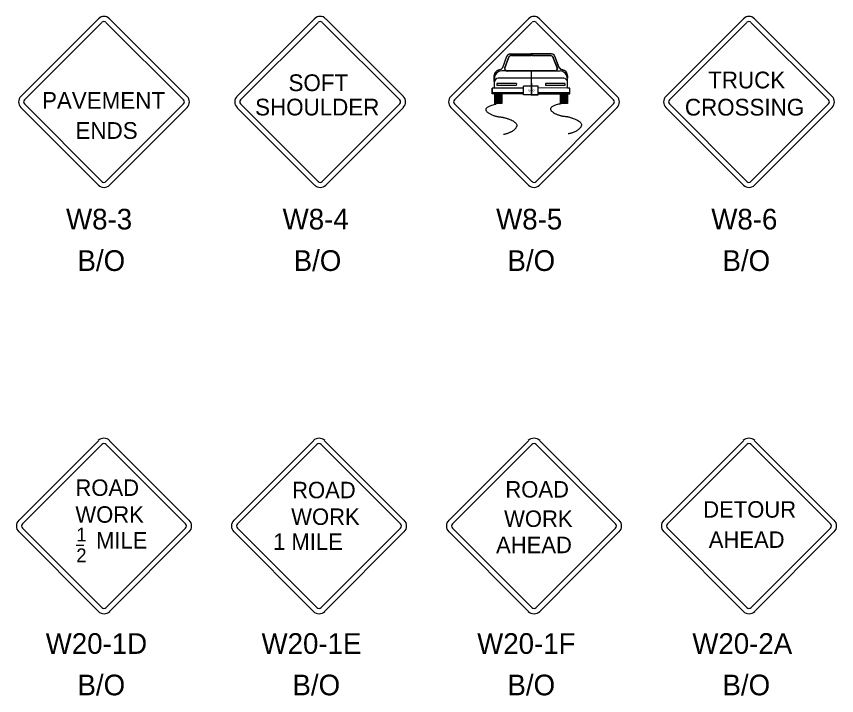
# Model space of a CAD drawing. Extents: x 10034 to 10794, y 10044 to 10499.
# Drawn here: x 10507.5 to 10646.3, y 10279.5 to 10394.4 of the extents above; entities that cross this region are included whole.
import ezdxf

# ---------------------------------------------------------------- set-up
doc = ezdxf.new("R2010")
doc.units = 0
for name, color, linetype in [('DSIndex', 7, 'Continuous'), ('DSText', 7, 'Continuous'), ('DSTitle', 7, 'Continuous'), ('PlotBorder_dp', 7, 'Continuous')]:
    doc.layers.add(name, color=color, linetype=linetype)

msp = doc.modelspace()

# ---------------------------------------------------------------- linework, layer by layer
at = {"layer": 'DSIndex'}
for p, q in [((10508.21, 10380.84), (10521.36, 10393.99)), ((10508.82, 10380.24), (10521.95, 10393.37)), ((10522.63, 10393.37), (10535.76, 10380.24)), ((10523.23, 10393.99), (10536.37, 10380.84)), ((10581, 10380.84), (10594.15, 10393.99)), ((10581.61, 10380.25), (10594.74, 10393.37)), ((10595.42, 10393.37), (10608.55, 10380.25)), ((10596.02, 10393.99), (10609.16, 10380.84)), ((10589.8, 10385.74), (10590.5, 10387.62)), ((10591.08, 10388.02), (10594.55, 10388.02)), ((10591.33, 10387.78), (10594.55, 10387.78)), ((10598.04, 10388.02), (10594.55, 10388.02)), ((10597.77, 10387.78), (10594.55, 10387.78)), ((10599.32, 10385.74), (10598.61, 10387.62)), ((10590.13, 10385.7), (10590.76, 10387.38)), ((10598.98, 10385.7), (10598.35, 10387.38)), ((10598.59, 10385.14), (10589.62, 10385.14)), ((10598.59, 10385.14), (10599.49, 10385.14)), ((10588.36, 10384.36), (10588.39, 10383.91)), ((10588.38, 10383.3), (10588.39, 10383.91)), ((10600.11, 10383.91), (10589, 10383.91)), ((10600.75, 10384.31), (10600.73, 10383.91)), ((10600.73, 10383.29), (10600.73, 10383.91)), ((10587.97, 10382.26), (10587.97, 10381.28)), ((10593.32, 10382.26), (10587.97, 10382.26)), ((10588.38, 10382.27), (10588.38, 10383.3)), ((10592.09, 10383), (10588.79, 10383)), ((10588.79, 10383), (10588.8, 10382.67)), ((10592.08, 10382.67), (10588.8, 10382.67)), ((10592.09, 10383), (10592.08, 10382.67)), ((10593.32, 10381.11), (10593.32, 10382.6)), ((10595.79, 10382.6), (10593.32, 10382.6)), ((10595.79, 10381.11), (10595.79, 10382.6)), ((10601.14, 10382.26), (10595.79, 10382.27)), ((10600.32, 10383), (10597.02, 10383)), ((10597.02, 10383), (10597.02, 10382.67)), ((10600.31, 10382.67), (10597.02, 10382.67)), ((10600.32, 10383), (10600.31, 10382.67)), ((10600.73, 10382.26), (10600.73, 10383.29)), ((10601.14, 10381.28), (10601.14, 10382.26)), ((10593.32, 10381.44), (10587.97, 10381.44)), ((10593.32, 10381.28), (10587.97, 10381.28)), ((10588.38, 10381.28), (10588.39, 10379.63)), ((10588.59, 10381.28), (10588.59, 10379.63)), ((10588.8, 10381.28), (10588.79, 10379.63)), ((10589, 10381.28), (10589, 10379.63)), ((10589.21, 10381.28), (10589.21, 10379.63)), ((10589.41, 10381.27), (10589.41, 10379.63)), ((10589.62, 10381.28), (10589.62, 10379.63)), ((10595.79, 10381.11), (10593.32, 10381.11)), ((10601.14, 10381.44), (10595.79, 10381.44)), ((10601.14, 10381.28), (10595.79, 10381.28)), ((10599.49, 10381.28), (10599.49, 10379.63)), ((10599.7, 10381.28), (10599.7, 10379.63)), ((10599.9, 10381.28), (10599.9, 10379.63)), ((10600.11, 10381.28), (10600.11, 10379.63)), ((10600.31, 10381.28), (10600.31, 10379.63)), ((10600.52, 10381.28), (10600.52, 10379.63)), ((10600.73, 10381.28), (10600.73, 10379.63)), ((10521.95, 10366.44), (10508.82, 10379.57)), ((10535.76, 10379.57), (10522.63, 10366.44)), ((10594.74, 10366.44), (10581.61, 10379.57)), ((10589.62, 10379.63), (10588.39, 10379.63)), ((10608.55, 10379.57), (10595.42, 10366.44)), ((10600.73, 10379.63), (10599.49, 10379.63)), ((10521.36, 10365.82), (10508.21, 10378.97)), ((10536.37, 10378.97), (10523.23, 10365.82)), ((10594.15, 10365.83), (10581, 10378.97)), ((10609.16, 10378.97), (10596.02, 10365.83)), ((10507.86, 10309.13), (10521.34, 10322.61)), ((10523.25, 10322.61), (10536.73, 10309.13)), ((10508.49, 10308.52), (10521.94, 10321.98)), ((10522.64, 10321.98), (10536.1, 10308.52)), ((10521.34, 10293.74), (10507.86, 10307.22)), ((10521.94, 10294.37), (10508.49, 10307.83)), ((10536.1, 10307.83), (10522.64, 10294.37)), ((10536.73, 10307.22), (10523.25, 10293.74)), ((10517.56, 10304.94), (10518.87, 10304.94))]:
    msp.add_line(p, q, dxfattribs=at)
for points in [[(10594.63, 10381.09), (10593.32, 10381.11), (10593.32, 10381.28), (10587.97, 10381.28), (10587.97, 10382.26), (10588.38, 10382.27), (10588.36, 10384.36), (10588.39, 10384.5), (10588.4, 10384.61), (10588.45, 10384.73), (10588.53, 10384.88), (10588.6, 10385), (10588.68, 10385.07), (10588.8, 10385.17), (10588.91, 10385.24), (10588.99, 10385.27), (10589.07, 10385.3), (10589.24, 10385.34), (10589.37, 10385.39), (10589.47, 10385.44), (10589.55, 10385.51), (10589.63, 10385.56), (10589.71, 10385.64), (10589.75, 10385.68), (10589.8, 10385.74), (10590.5, 10387.62), (10590.55, 10387.72), (10590.6, 10387.81), (10590.67, 10387.86), (10590.75, 10387.91), (10590.81, 10387.96), (10590.89, 10387.99), (10591.02, 10388.02), (10591.08, 10388.02), (10594.7, 10388.02), (10594.69, 10387.78), (10591.33, 10387.78), (10591.22, 10387.76), (10591.13, 10387.73), (10591.05, 10387.7), (10590.99, 10387.65), (10590.92, 10387.62), (10590.86, 10387.58), (10590.81, 10387.51), (10590.76, 10387.38), (10590.13, 10385.7), (10590.11, 10385.59), (10590.12, 10385.48), (10590.17, 10385.37), (10590.22, 10385.25), (10590.32, 10385.19), (10590.41, 10385.14), (10590.6, 10385.13), (10594.6, 10385.14)], [(10594.62, 10381.11), (10595.79, 10381.11), (10595.79, 10381.28), (10601.14, 10381.28), (10601.14, 10382.26), (10600.73, 10382.26), (10600.73, 10383.91), (10600.72, 10384.04), (10600.73, 10384.15), (10600.74, 10384.33), (10600.73, 10384.48), (10600.71, 10384.63), (10600.66, 10384.73), (10600.61, 10384.85), (10600.51, 10384.98), (10600.41, 10385.1), (10600.32, 10385.18), (10600.19, 10385.23), (10600.03, 10385.3), (10599.92, 10385.33), (10599.74, 10385.38), (10599.63, 10385.44), (10599.53, 10385.52), (10599.44, 10385.64), (10599.34, 10385.71), (10599.31, 10385.74), (10598.61, 10387.62), (10598.56, 10387.7), (10598.51, 10387.78), (10598.48, 10387.85), (10598.42, 10387.91), (10598.33, 10387.94), (10598.24, 10387.98), (10598.04, 10388.02), (10594.69, 10388.01), (10594.71, 10387.78), (10597.77, 10387.78), (10597.89, 10387.77), (10597.98, 10387.74), (10598.07, 10387.68), (10598.18, 10387.63), (10598.27, 10387.55), (10598.32, 10387.47), (10598.35, 10387.38), (10598.98, 10385.7), (10598.98, 10385.62), (10599.01, 10385.54), (10599, 10385.47), (10598.98, 10385.4), (10598.94, 10385.34), (10598.9, 10385.29), (10598.87, 10385.22), (10598.76, 10385.17), (10598.73, 10385.17), (10598.64, 10385.13), (10594.59, 10385.13)]]:
    msp.add_lwpolyline(points, close=True, dxfattribs=at)
for centre, radius, start, end in [((10522.29, 10393.05), 1.32, 45, 135), ((10522.29, 10393.04), 0.478, 45, 135), ((10595.08, 10393.05), 1.32, 45, 135), ((10595.08, 10393.04), 0.478, 45, 135), ((10591.07, 10387.41), 0.617, 89.9999, 159.5728), ((10591.33, 10387.16), 0.617, 89.9999, 159.5806), ((10597.77, 10387.16), 0.617, 20.4192, 89.9999), ((10589.39, 10384.33), 1.03, 102.0025, 178.0644), ((10589.62, 10383.91), 1.23, 89.9999, 179.9999), ((10588.96, 10386.34), 1.03, 281.9867, 324.0057), ((10590.52, 10385.55), 0.411, 159.5922, 269.9999), ((10598.59, 10385.55), 0.411, 269.9999, 20.4076), ((10600.14, 10386.34), 1.03, 215.9941, 258.0132), ((10599.49, 10383.91), 1.23, 359.9999, 89.9999), ((10599.72, 10384.33), 1.03, 358.9918, 77.9966), ((10589, 10383.29), 0.617, 89.9999, 179.9999), ((10600.11, 10383.29), 0.617, 359.9999, 89.9999), ((10509.15, 10379.91), 1.32, 135, 225), ((10535.43, 10379.91), 1.32, 315, 45), ((10581.94, 10379.91), 1.32, 135, 225), ((10608.22, 10379.91), 1.32, 315, 45), ((10509.16, 10379.91), 0.478, 135, 225), ((10535.43, 10379.91), 0.478, 315, 45), ((10581.95, 10379.91), 0.478, 135, 225), ((10608.21, 10379.91), 0.478, 315, 45), ((10522.3, 10366.76), 1.32, 225, 315), ((10522.29, 10366.77), 0.478, 225, 315), ((10595.08, 10366.76), 1.32, 225, 315), ((10595.08, 10366.77), 0.478, 225, 315), ((10522.29, 10321.65), 1.36, 45, 135), ((10522.29, 10321.64), 0.49, 45, 135), ((10508.82, 10308.18), 1.36, 135, 225), ((10508.83, 10308.18), 0.49, 135, 225), ((10535.75, 10308.18), 0.49, 315, 45), ((10535.76, 10308.18), 1.36, 315, 45), ((10522.3, 10294.7), 1.36, 225, 315), ((10522.29, 10294.72), 0.49, 225, 315)]:
    msp.add_arc(centre, radius, start, end, dxfattribs=at)
for points in [[(10588.7, 10379.5), (10586.27, 10378.98), (10588.08, 10377.42), (10589.88, 10377.32)], [(10599.64, 10379.6), (10597.22, 10379.08), (10599.02, 10377.52), (10600.83, 10377.42)], [(10589.73, 10377.34), (10592.53, 10376.62), (10591.69, 10374.77), (10589.91, 10374.39)], [(10600.68, 10377.44), (10603.48, 10376.72), (10602.64, 10374.87), (10600.85, 10374.49)]]:
    msp.add_open_spline(points, degree=2, dxfattribs=at)
at = {"layer": 'DSText'}
for p, q in [((10544.8, 10380.84), (10557.95, 10393.99)), ((10559.82, 10393.99), (10572.97, 10380.84)), ((10617.39, 10380.84), (10630.54, 10393.99)), ((10632.41, 10393.99), (10645.55, 10380.84)), ((10557.95, 10365.82), (10544.8, 10378.97)), ((10572.97, 10378.97), (10559.82, 10365.82)), ((10630.54, 10365.82), (10617.39, 10378.97)), ((10645.55, 10378.97), (10632.41, 10365.82)), ((10544.25, 10309.13), (10557.73, 10322.61)), ((10559.64, 10322.61), (10573.12, 10309.13)), ((10580.65, 10309.13), (10594.12, 10322.61)), ((10596.04, 10322.61), (10609.51, 10309.13)), ((10617.04, 10309.13), (10630.52, 10322.61)), ((10632.43, 10322.61), (10645.91, 10309.13)), ((10557.73, 10293.74), (10544.25, 10307.22)), ((10573.12, 10307.22), (10559.64, 10293.74)), ((10594.12, 10293.74), (10580.65, 10307.22)), ((10609.51, 10307.22), (10596.04, 10293.74)), ((10630.52, 10293.74), (10617.04, 10307.22)), ((10645.91, 10307.22), (10632.43, 10293.74))]:
    msp.add_line(p, q, dxfattribs=at)
for centre, radius, start, end in [((10558.88, 10393.05), 1.32, 45, 135), ((10631.47, 10393.05), 1.32, 45, 135), ((10545.74, 10379.91), 1.32, 135, 225), ((10572.02, 10379.91), 1.32, 315, 45), ((10618.33, 10379.91), 1.32, 135, 225), ((10644.61, 10379.91), 1.32, 315, 45), ((10558.89, 10366.76), 1.32, 225, 315), ((10631.48, 10366.76), 1.32, 225, 315), ((10558.69, 10321.65), 1.36, 45, 135), ((10595.08, 10321.65), 1.36, 45, 135), ((10631.47, 10321.65), 1.36, 45, 135), ((10545.22, 10308.18), 1.36, 135, 225), ((10572.16, 10308.18), 1.36, 315, 45), ((10581.61, 10308.18), 1.36, 135, 225), ((10608.55, 10308.18), 1.36, 315, 45), ((10618, 10308.18), 1.36, 135, 225), ((10644.94, 10308.18), 1.36, 315, 45), ((10558.69, 10294.7), 1.36, 225, 315), ((10595.08, 10294.7), 1.36, 225, 315), ((10631.48, 10294.7), 1.36, 225, 315)]:
    msp.add_arc(centre, radius, start, end, dxfattribs=at)
at = {"layer": 'DSTitle'}
for p, q in [((10545.42, 10380.24), (10558.55, 10393.37)), ((10559.23, 10393.37), (10572.35, 10380.24)), ((10618, 10380.24), (10631.13, 10393.37)), ((10631.81, 10393.37), (10644.94, 10380.24)), ((10558.55, 10366.44), (10545.42, 10379.56)), ((10572.35, 10379.56), (10559.23, 10366.44)), ((10631.13, 10366.44), (10618, 10379.57)), ((10644.94, 10379.57), (10631.81, 10366.44)), ((10544.88, 10308.52), (10558.34, 10321.98)), ((10559.03, 10321.98), (10572.49, 10308.52)), ((10581.27, 10308.52), (10594.73, 10321.98)), ((10595.43, 10321.98), (10608.89, 10308.52)), ((10617.67, 10308.52), (10631.12, 10321.98)), ((10631.82, 10321.98), (10645.28, 10308.52)), ((10558.34, 10294.37), (10544.88, 10307.83)), ((10572.49, 10307.83), (10559.03, 10294.37)), ((10594.73, 10294.37), (10581.27, 10307.83)), ((10608.89, 10307.83), (10595.43, 10294.37)), ((10631.12, 10294.37), (10617.67, 10307.83)), ((10645.28, 10307.83), (10631.82, 10294.37))]:
    msp.add_line(p, q, dxfattribs=at)
for centre, radius, start, end in [((10558.88, 10393.04), 0.478, 45, 135), ((10631.47, 10393.04), 0.478, 45, 135), ((10545.75, 10379.91), 0.478, 135, 225), ((10572.02, 10379.91), 0.478, 315, 45), ((10618.34, 10379.91), 0.478, 135, 225), ((10644.6, 10379.91), 0.478, 315, 45), ((10558.88, 10366.77), 0.478, 225, 315), ((10631.47, 10366.77), 0.478, 225, 315), ((10558.69, 10321.64), 0.49, 45, 135), ((10595.08, 10321.64), 0.49, 45, 135), ((10631.47, 10321.64), 0.49, 45, 135), ((10545.23, 10308.18), 0.49, 135, 225), ((10572.15, 10308.18), 0.49, 315, 45), ((10581.62, 10308.18), 0.49, 135, 225), ((10608.54, 10308.18), 0.49, 315, 45), ((10618.01, 10308.18), 0.49, 135, 225), ((10644.93, 10308.18), 0.49, 315, 45), ((10558.69, 10294.72), 0.49, 225, 315), ((10595.08, 10294.72), 0.49, 225, 315), ((10631.47, 10294.72), 0.49, 225, 315)]:
    msp.add_arc(centre, radius, start, end, dxfattribs=at)

# ---------------------------------------------------------------- texts
at = {"layer": 'DSIndex'}
for s, height, p in [('PAVEMENT', 2.831, (10511.8, 10378.75)), ('ENDS', 2.831, (10517.47, 10373.66)), ('W8-3', 3.5, (10515.87, 10358.33)), ('W8-5', 3.5, (10588.67, 10358.33)), ('B/O', 3.5, (10517.81, 10351.32)), ('B/O', 3.5, (10590.59, 10351.32)), ('ROAD', 2.786, (10517.46, 10313.27)), ('WORK', 2.786, (10517.45, 10308.73)), ('1', 2.32, (10517.61, 10305.57)), ('MILE', 2.786, (10520.95, 10304.36)), ('2', 2.32, (10517.61, 10302.06)), ('W20-1D', 3.5, (10512.43, 10286.55)), ('B/O', 3.5, (10517.81, 10279.54))]:
    msp.add_text(s, height=height, dxfattribs=at).set_placement(p)
msp.add_text('GKO', height=0.348, rotation=0.009, dxfattribs=at).set_placement((10594.1, 10381.7))
at = {"layer": 'PlotBorder_dp'}
for s, height, p in [('TRUCK', 2.831, (10624.56, 10382.2)), ('SOFT', 2.831, (10553.52, 10381.74)), ('SHOULDER', 2.831, (10547.87, 10377.62)), ('CROSSING', 2.831, (10620.62, 10377.6)), ('W8-4', 3.5, (10552.53, 10358.33)), ('W8-6', 3.5, (10625.09, 10358.33)), ('B/O', 3.5, (10554.4, 10351.32)), ('B/O', 3.5, (10626.99, 10351.32)), ('ROAD', 2.786, (10554.13, 10312.87)), ('ROAD', 2.786, (10590.23, 10312.99)), ('DETOUR', 2.786, (10623.72, 10309.59)), ('WORK', 2.786, (10553.98, 10308.36)), ('WORK', 2.786, (10590.02, 10308.02)), ('AHEAD', 2.786, (10624.66, 10304.48)), ('1 MILE', 2.786, (10550.91, 10304.14)), ('AHEAD', 2.786, (10588.66, 10303.58)), ('W20-1E', 3.5, (10548.96, 10286.55)), ('W20-1F', 3.5, (10585.46, 10286.55)), ('W20-2A', 3.5, (10621.88, 10286.55)), ('B/O', 3.5, (10554.2, 10279.54)), ('B/O', 3.5, (10590.59, 10279.54)), ('B/O', 3.5, (10626.99, 10279.54))]:
    msp.add_text(s, height=height, dxfattribs=at).set_placement(p)

doc.saveas('drawing.dxf')
